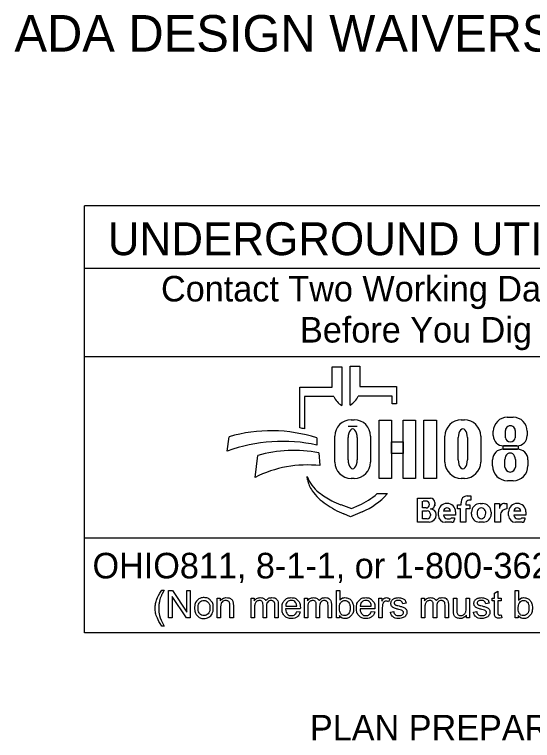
# Model space of a CAD drawing. Extents: x -4 to 116, y -17 to 29.
# Drawn here: x 86.475 to 89.311, y 9.561 to 13.536 of the extents above; entities that cross this region are included whole.
import ezdxf

# ---------------------------------------------------------------- set-up
doc = ezdxf.new("R2010")
doc.units = 0
doc.layers.add('SH_Data', color=7, linetype='Continuous')
doc.layers.add('SH_Text', color=7, linetype='Continuous')

msp = doc.modelspace()

# ---------------------------------------------------------------- linework, layer by layer
at = {"layer": 'SH_Data'}
for p, q in [((86.8574, 10.1506), (86.8574, 12.4881)), ((91.1074, 12.4881), (86.8574, 12.4881)), ((86.8574, 12.1466), (91.1074, 12.1466)), ((86.8574, 11.6632), (91.1074, 11.6632)), ((91.1074, 10.6685), (86.8574, 10.6685)), ((91.1074, 10.1506), (86.8574, 10.1506))]:
    msp.add_line(p, q, dxfattribs=at)
at = {"layer": 'SH_Text'}
for p, q in [((88.3127, 11.3979), (88.3127, 11.61)), ((88.3127, 11.61), (88.3663, 11.61)), ((88.3663, 11.61), (88.3663, 11.4985)), ((88.2134, 11.4961), (88.2134, 11.6076)), ((88.2134, 11.6076), (88.267, 11.6076)), ((88.267, 11.6076), (88.267, 11.3956)), ((88.0374, 11.2723), (88.0374, 11.4961)), ((88.0374, 11.4961), (88.2134, 11.4961)), ((88.3663, 11.4985), (88.5656, 11.4985)), ((88.5656, 11.4985), (88.5656, 11.4046)), ((88.0627, 11.4447), (88.0627, 11.2678)), ((88.2238, 11.4447), (88.0627, 11.4447)), ((88.5423, 11.447), (88.3559, 11.447)), ((88.5423, 11.4046), (88.5423, 11.447)), ((88.5656, 11.4046), (88.5423, 11.4046)), ((89.1729, 11.331), (89.2057, 11.331)), ((88.3184, 11.317), (88.3349, 11.317)), ((88.9214, 11.317), (88.938, 11.317)), ((88.3516, 11.2799), (88.3018, 11.2799)), ((89.0966, 11.2303), (89.0966, 11.2546)), ((89.1628, 11.219), (89.1628, 11.2583)), ((89.217, 11.2583), (89.217, 11.219)), ((89.282, 11.2546), (89.282, 11.2303)), ((87.6401, 11.1459), (87.6494, 11.2241)), ((88.1307, 11.2176), (88.1307, 11.1788)), ((88.2289, 11.0855), (88.2289, 11.2275)), ((88.3018, 11.0969), (88.3018, 11.2192)), ((88.3516, 11.2192), (88.3516, 11.0969)), ((88.4244, 11.2275), (88.4244, 11.0855)), ((88.8319, 11.0855), (88.8319, 11.2275)), ((88.9049, 11.0969), (88.9049, 11.2192)), ((88.9546, 11.2192), (88.9546, 11.0969)), ((89.0274, 11.2275), (89.0274, 11.0855)), ((89.226, 11.1743), (89.1526, 11.1743)), ((88.1407, 11.137), (88.1469, 11.066)), ((89.1508, 11.156), (89.2282, 11.156)), ((87.7919, 11.0014), (87.8066, 11.1216)), ((89.0929, 11.0641), (89.0929, 11.0982)), ((89.1604, 11.0582), (89.1604, 11.0991)), ((89.2173, 11.0991), (89.2173, 11.0582)), ((89.286, 11.0982), (89.286, 11.0641)), ((88.0796, 10.9885), (88.0765, 11.0064)), ((88.3349, 10.996), (88.3184, 10.996)), ((88.938, 10.996), (88.9214, 10.996)), ((89.2051, 10.9832), (89.1739, 10.9832)), ((88.4599, 10.9126), (88.5173, 10.9126)), ((88.9537, 10.9004), (88.9732, 10.9004)), ((88.9732, 10.9004), (88.9732, 10.8774)), ((88.6812, 10.7569), (88.6812, 10.8876)), ((88.6812, 10.8876), (88.7523, 10.8876)), ((88.7091, 10.8341), (88.7091, 10.8711)), ((88.7343, 10.8711), (88.7131, 10.8711)), ((88.7761, 10.8639), (88.7761, 10.856)), ((88.9205, 10.852), (88.9205, 10.8625)), ((88.9466, 10.8605), (88.9466, 10.852)), ((88.9732, 10.8769), (88.9631, 10.8769)), ((89.025, 10.8586), (89.0371, 10.8586)), ((89.1052, 10.7557), (89.1052, 10.8584)), ((89.1052, 10.8584), (89.1298, 10.8584)), ((89.1298, 10.8584), (89.1298, 10.8315)), ((89.157, 10.8584), (89.1709, 10.8584)), ((89.1709, 10.8584), (89.1709, 10.8287)), ((88.2614, 10.8523), (88.3209, 10.8318)), ((88.3209, 10.8318), (88.3619, 10.8496)), ((88.7285, 10.8341), (88.7091, 10.8341)), ((88.7091, 10.7747), (88.7091, 10.8176)), ((88.7091, 10.8176), (88.7347, 10.8176)), ((88.8623, 10.8161), (88.8238, 10.8161)), ((88.9011, 10.829), (88.9011, 10.852)), ((88.9011, 10.852), (88.9205, 10.852)), ((88.9161, 10.829), (88.9011, 10.829)), ((88.9161, 10.7557), (88.9161, 10.829)), ((88.9466, 10.852), (88.9681, 10.852)), ((88.9681, 10.829), (88.9466, 10.829)), ((88.9466, 10.829), (88.9466, 10.7557)), ((88.9681, 10.852), (88.9681, 10.829)), ((89.2472, 10.8161), (89.2087, 10.8161)), ((88.3148, 10.7848), (88.2775, 10.8012)), ((88.3781, 10.8122), (88.3148, 10.7848)), ((88.7344, 10.7747), (88.7091, 10.7747)), ((88.7528, 10.7995), (88.7528, 10.7931)), ((88.7842, 10.7966), (88.7842, 10.7962)), ((88.7957, 10.7937), (88.7957, 10.8121)), ((88.8902, 10.7944), (88.8238, 10.7944)), ((88.8447, 10.7752), (88.8589, 10.7752)), ((88.8674, 10.7807), (88.8843, 10.7807)), ((88.8843, 10.7807), (88.8843, 10.7709)), ((88.8902, 10.8121), (88.8902, 10.7944)), ((88.9771, 10.8), (88.9771, 10.8108)), ((89.0849, 10.8108), (89.0849, 10.8)), ((89.1357, 10.7938), (89.1357, 10.7557)), ((89.1806, 10.7937), (89.1806, 10.8121)), ((89.2752, 10.7944), (89.2087, 10.7944)), ((89.2297, 10.7752), (89.2438, 10.7752)), ((89.2524, 10.7807), (89.2692, 10.7807)), ((89.2692, 10.7807), (89.2692, 10.7709)), ((89.2752, 10.8121), (89.2752, 10.7944)), ((88.7448, 10.7569), (88.6812, 10.7569)), ((88.8691, 10.7557), (88.8337, 10.7557)), ((88.9466, 10.7557), (88.9161, 10.7557)), ((89.0421, 10.7572), (89.0199, 10.7572)), ((89.1357, 10.7557), (89.1052, 10.7557)), ((89.254, 10.7557), (89.2186, 10.7557))]:
    msp.add_line(p, q, dxfattribs=at)
for points in [[(88.4708, 11.3159), (88.5388, 11.3159), (88.5388, 10.9959), (88.4708, 10.9959)], [(88.603, 11.3159), (88.6709, 11.3159), (88.6709, 10.9959), (88.603, 10.9959)], [(88.7163, 11.3159), (88.785, 11.3159), (88.785, 10.9959), (88.7163, 10.9959)], [(88.5388, 11.196), (88.603, 11.196), (88.603, 11.132), (88.5388, 11.132)], [(89.1505, 11.1744), (89.2322, 11.1744), (89.2322, 11.1559), (89.1505, 11.1559)]]:
    msp.add_lwpolyline(points, close=True, dxfattribs=at)
for points in [[(87.282, 10.3844), (87.2951, 10.3844)], [(87.3187, 10.2318), (87.3187, 10.3819), (87.339, 10.3819), (87.418, 10.264), (87.418, 10.3819), (87.437, 10.3819), (87.437, 10.2318), (87.4167, 10.2318), (87.3377, 10.3497), (87.3377, 10.2318), (87.3187, 10.2318)], [(88.2542, 10.2318), (88.2371, 10.2318), (88.2371, 10.3819), (88.2555, 10.3819), (88.2555, 10.3284)], [(89.1031, 10.2636), (89.1031, 10.3263), (89.0895, 10.3263), (89.0895, 10.3406), (89.1031, 10.3406), (89.1031, 10.3675), (89.1215, 10.3786), (89.1215, 10.3406), (89.14, 10.3406), (89.14, 10.3263), (89.1215, 10.3263), (89.1215, 10.2625)], [(89.2332, 10.2318), (89.2162, 10.2318), (89.2162, 10.3819), (89.2346, 10.3819), (89.2346, 10.3284)], [(87.5847, 10.2318), (87.5847, 10.3406), (87.6013, 10.3406), (87.6013, 10.3251)], [(87.7711, 10.2318), (87.7711, 10.3406), (87.7876, 10.3406), (87.7876, 10.3252)], [(88.0625, 10.2318), (88.0625, 10.3406), (88.0789, 10.3406), (88.0789, 10.3252)], [(88.4702, 10.2318), (88.4702, 10.3406), (88.4868, 10.3406), (88.4868, 10.3241)], [(88.5293, 10.3371), (88.5228, 10.3201)], [(88.7035, 10.2318), (88.7035, 10.3406), (88.7199, 10.3406), (88.7199, 10.3252)], [(88.8778, 10.2732), (88.8778, 10.3406), (88.8962, 10.3406), (88.8962, 10.2803)], [(88.9475, 10.2823), (88.9475, 10.3406), (88.9659, 10.3406), (88.9659, 10.2318), (88.9494, 10.2318)], [(87.673, 10.2987), (87.673, 10.2318), (87.6546, 10.2318), (87.6546, 10.2979)], [(87.8542, 10.2949), (87.8542, 10.2318), (87.8357, 10.2318), (87.8357, 10.3024)], [(87.9186, 10.3064), (87.9186, 10.2318), (87.9002, 10.2318), (87.9002, 10.3003)], [(88.1455, 10.2949), (88.1455, 10.2318), (88.1271, 10.2318), (88.1271, 10.3024)], [(88.21, 10.3064), (88.21, 10.2318), (88.1916, 10.2318), (88.1916, 10.3003)], [(88.6192, 10.3124), (88.6012, 10.31)], [(88.7865, 10.2949), (88.7865, 10.2318), (88.7681, 10.2318), (88.7681, 10.3024)], [(88.851, 10.3064), (88.851, 10.2318), (88.8326, 10.2318), (88.8326, 10.3003)], [(89.0738, 10.3124), (89.0557, 10.31)], [(87.6031, 10.2911), (87.6031, 10.2318), (87.5847, 10.2318)], [(87.7895, 10.2882), (87.7895, 10.2318), (87.7711, 10.2318)], [(88.0398, 10.2814), (87.9587, 10.2814)], [(87.9597, 10.2965), (88.0205, 10.2965)], [(88.0203, 10.2669), (88.0393, 10.2645)], [(88.0809, 10.2882), (88.0809, 10.2318), (88.0625, 10.2318)], [(88.4478, 10.2814), (88.3667, 10.2814)], [(88.3677, 10.2965), (88.4285, 10.2965)], [(88.4283, 10.2669), (88.4473, 10.2645)], [(88.4887, 10.2888), (88.4887, 10.2318), (88.4702, 10.2318)], [(88.5328, 10.2643), (88.551, 10.2671)], [(88.7219, 10.2882), (88.7219, 10.2318), (88.7035, 10.2318)], [(88.9874, 10.2643), (89.0056, 10.2671)], [(88.2542, 10.2454), (88.2542, 10.2318)], [(88.9494, 10.2318), (88.9494, 10.2478)], [(89.14, 10.2482), (89.1426, 10.2319)], [(89.2332, 10.2454), (89.2332, 10.2318)], [(87.2951, 10.1876), (87.282, 10.1876)]]:
    msp.add_lwpolyline(points, dxfattribs=at)
for centre, radius, start, end in [((88.3151, 11.4815), 0.0985, 201.9296, 240.7469), ((88.2646, 11.4838), 0.0985, 299.2531, 338.0704), ((89.1729, 11.2546), 0.0763, 90, 180), ((89.2057, 11.2546), 0.0763, 0, 90), ((88.3184, 11.2275), 0.0895, 90, 180), ((88.3349, 11.2275), 0.0895, 0, 90), ((88.9214, 11.2275), 0.0895, 90, 180), ((88.938, 11.2275), 0.0895, 0, 90), ((87.8795, 10.438), 0.8191, 72.1402, 106.3144), ((87.9093, 10.4633), 0.8191, 79.2074, 81.0007), ((89.1526, 11.2303), 0.056, 180, 270), ((89.226, 11.2303), 0.056, 270, 0), ((87.9426, 10.3069), 0.8919, 77.8238, 109.8274), ((88.0065, 10.4172), 0.7322, 79.44, 105.8467), ((89.1508, 11.0982), 0.0579, 90, 180), ((89.2282, 11.0982), 0.0579, 0, 90), ((88.0785, 10.434), 0.6357, 83.8248, 116.8021), ((88.3184, 11.0855), 0.0895, 180, 270), ((88.3349, 11.0855), 0.0895, 270, 0), ((88.9214, 11.0855), 0.0895, 180, 270), ((88.938, 11.0855), 0.0895, 270, 0), ((89.1739, 11.0641), 0.081, 180, 270), ((89.2051, 11.0641), 0.081, 270, 0), ((88.2639, 11.0785), 0.2008, 201.0457, 232.5314), ((88.2209, 11.0126), 0.1433, 189.6817, 216.0884), ((88.3546, 11.1101), 0.3088, 216.0884, 235.7167), ((88.4565, 11.3298), 0.5173, 232.5314, 241.794), ((88.2185, 11.1801), 0.3602, 293.4582, 312.0712), ((88.2185, 11.1801), 0.401, 293.4582, 317.8286), ((88.9537, 10.8669), 0.0335, 90, 187.5187), ((88.5211, 11.3543), 0.6044, 235.7167, 246.2325), ((88.3713, 11.1709), 0.3371, 241.794, 250.9821), ((88.7285, 10.8529), 0.0187, 270, 2.0582), ((88.7304, 10.8542), 0.0169, 357.8325, 90), ((88.7519, 10.8531), 0.0243, 270, 6.6529), ((88.7523, 10.8639), 0.0238, 0, 90), ((88.843, 10.8121), 0.0473, 0, 180), ((88.9631, 10.8605), 0.0165, 90, 180), ((89.025, 10.8108), 0.0478, 90, 180), ((89.0371, 10.8108), 0.0478, 0, 90), ((89.1567, 10.8315), 0.0269, 89.2449, 180), ((89.2279, 10.8121), 0.0473, 0, 180), ((88.7347, 10.7995), 0.0181, 0, 90), ((88.7521, 10.7967), 0.0321, 4.0748, 90), ((88.7625, 10.8517), 0.0175, 347.4023, 0), ((88.843, 10.8151), 0.0193, 2.9632, 177.0368), ((89.1706, 10.7938), 0.0349, 89.6033, 180), ((89.2279, 10.8151), 0.0193, 2.9632, 177.0368), ((88.7344, 10.7931), 0.0184, 270, 0), ((88.7448, 10.7962), 0.0393, 270, 0), ((88.7512, 10.7966), 0.033, 0, 11.7502), ((88.8337, 10.7937), 0.038, 180, 270), ((88.8447, 10.7962), 0.021, 184.827, 270), ((88.8589, 10.7846), 0.00938, 270, 335.9979), ((89.0199, 10.8), 0.0428, 180, 270), ((89.0421, 10.8), 0.0428, 270, 0), ((89.2186, 10.7937), 0.038, 180, 270), ((89.2297, 10.7962), 0.021, 184.827, 270), ((89.2438, 10.7846), 0.00938, 270, 335.9979), ((88.8691, 10.7709), 0.0152, 270, 0), ((89.254, 10.7709), 0.0152, 270, 0)]:
    msp.add_arc(centre, radius, start, end, dxfattribs=at)
for centre, major_axis, ratio, start_param, end_param in [((88.3267, 11.2192), (0, 0.0484), 0.514403, 4.712389, 7.853982), ((88.9298, 11.2192), (0, 0.0484), 0.514403, 4.712389, 7.853982), ((89.1899, 11.2583), (0.0271, 0), 0.969373, 0, 3.141593), ((89.1899, 11.219), (0.0271, 0), 0.818453, 3.141593, 6.283185), ((89.1889, 11.0991), (0, 0.0358), 0.794529, 4.712389, 7.853982), ((88.3267, 11.0969), (0, 0.0484), 0.514403, 1.570796, 4.712389), ((88.9298, 11.0969), (0, 0.0484), 0.514403, 1.570796, 4.712389), ((89.1889, 11.0582), (0.0284, 0), 0.959837, 3.141593, 6.283185), ((89.0315, 10.8054), (0, 0.029), 0.832186, 4.712389, 7.853982), ((89.0315, 10.8054), (0, 0.0302), 0.797287, 1.570796, 4.712389)]:
    msp.add_ellipse(centre, major_axis=major_axis, ratio=ratio, start_param=start_param, end_param=end_param, dxfattribs=at)
for points in [[(87.282, 10.1876), (87.2667, 10.2068), (87.2561, 10.2327), (87.2456, 10.2585), (87.2456, 10.2861), (87.2456, 10.3105), (87.2535, 10.3328), (87.2627, 10.3587), (87.282, 10.3844)], [(87.2951, 10.3844), (87.2828, 10.3631), (87.2788, 10.354), (87.2726, 10.3399), (87.269, 10.3245), (87.2646, 10.3054), (87.2646, 10.286), (87.2646, 10.2367), (87.2951, 10.1876)], [(87.4612, 10.2862), (87.4612, 10.3164), (87.478, 10.3309), (87.492, 10.343), (87.5122, 10.343), (87.5346, 10.343), (87.5488, 10.3283), (87.563, 10.3136), (87.563, 10.2877), (87.563, 10.2667), (87.5568, 10.2547), (87.5505, 10.2427), (87.5384, 10.236), (87.5264, 10.2294), (87.5122, 10.2294), (87.4893, 10.2294), (87.4753, 10.244), (87.4612, 10.2586), (87.4612, 10.2862)], [(87.6013, 10.3251), (87.6132, 10.343), (87.6359, 10.343), (87.6457, 10.343), (87.6539, 10.3395), (87.6622, 10.3359), (87.6663, 10.3302), (87.6704, 10.3245), (87.672, 10.3166), (87.673, 10.3115), (87.673, 10.2987)], [(87.7876, 10.3252), (87.7927, 10.3333), (87.8012, 10.3381), (87.8097, 10.343), (87.8206, 10.343), (87.8327, 10.343), (87.8404, 10.338), (87.8481, 10.3329), (87.8513, 10.3239), (87.8642, 10.343), (87.885, 10.343), (87.9012, 10.343), (87.9099, 10.334), (87.9186, 10.3251), (87.9186, 10.3064)], [(88.0393, 10.2645), (88.0348, 10.2478), (88.0226, 10.2386), (88.0104, 10.2294), (87.9915, 10.2294), (87.9676, 10.2294), (87.9537, 10.2441), (87.9397, 10.2587), (87.9397, 10.2853), (87.9397, 10.3127), (87.9538, 10.3279), (87.9679, 10.343), (87.9905, 10.343), (88.0123, 10.343), (88.0261, 10.3282), (88.0399, 10.3133), (88.0399, 10.2864), (88.0399, 10.2847), (88.0398, 10.2814)], [(88.0789, 10.3252), (88.0841, 10.3333), (88.0926, 10.3381), (88.1011, 10.343), (88.1119, 10.343), (88.124, 10.343), (88.1318, 10.338), (88.1395, 10.3329), (88.1427, 10.3239), (88.1556, 10.343), (88.1763, 10.343), (88.1925, 10.343), (88.2013, 10.334), (88.21, 10.3251), (88.21, 10.3064)], [(88.2555, 10.3284), (88.2672, 10.343), (88.2853, 10.343), (88.2954, 10.343), (88.3043, 10.339), (88.3133, 10.3349), (88.3191, 10.3276), (88.3249, 10.3203), (88.3281, 10.3099), (88.3314, 10.2996), (88.3314, 10.2878), (88.3314, 10.2599), (88.3176, 10.2446), (88.3038, 10.2294), (88.2844, 10.2294), (88.2651, 10.2294), (88.2542, 10.2454)], [(88.4473, 10.2645), (88.4428, 10.2478), (88.4306, 10.2386), (88.4184, 10.2294), (88.3995, 10.2294), (88.3756, 10.2294), (88.3617, 10.2441), (88.3477, 10.2587), (88.3477, 10.2853), (88.3477, 10.3127), (88.3618, 10.3279), (88.3759, 10.343), (88.3985, 10.343), (88.4203, 10.343), (88.4341, 10.3282), (88.4479, 10.3133), (88.4479, 10.2864), (88.4479, 10.2847), (88.4478, 10.2814)], [(88.4868, 10.3241), (88.4932, 10.3357), (88.4986, 10.3393), (88.5039, 10.343), (88.5104, 10.343), (88.5197, 10.343), (88.5293, 10.3371)], [(88.551, 10.2671), (88.5526, 10.2562), (88.5596, 10.2503), (88.5667, 10.2445), (88.5793, 10.2445), (88.592, 10.2445), (88.5982, 10.2496), (88.6044, 10.2548), (88.6044, 10.2618), (88.6044, 10.2681), (88.5989, 10.2717), (88.5951, 10.2741), (88.58, 10.2779), (88.5597, 10.283), (88.5519, 10.2868), (88.544, 10.2905), (88.54, 10.2971), (88.5359, 10.3037), (88.5359, 10.3117), (88.5359, 10.319), (88.5393, 10.3251), (88.5426, 10.3313), (88.5483, 10.3354), (88.5527, 10.3386), (88.5601, 10.3408), (88.5675, 10.343), (88.5761, 10.343), (88.5889, 10.343), (88.5986, 10.3393), (88.6083, 10.3356), (88.6129, 10.3293), (88.6175, 10.323), (88.6192, 10.3124)], [(88.7199, 10.3252), (88.7251, 10.3333), (88.7336, 10.3381), (88.7421, 10.343), (88.7529, 10.343), (88.765, 10.343), (88.7728, 10.338), (88.7805, 10.3329), (88.7837, 10.3239), (88.7966, 10.343), (88.8173, 10.343), (88.8335, 10.343), (88.8423, 10.334), (88.851, 10.3251), (88.851, 10.3064)], [(89.0056, 10.2671), (89.0072, 10.2562), (89.0142, 10.2503), (89.0212, 10.2445), (89.0339, 10.2445), (89.0466, 10.2445), (89.0528, 10.2496), (89.0589, 10.2548), (89.0589, 10.2618), (89.0589, 10.2681), (89.0535, 10.2717), (89.0497, 10.2741), (89.0346, 10.2779), (89.0143, 10.283), (89.0065, 10.2868), (88.9986, 10.2905), (88.9946, 10.2971), (88.9905, 10.3037), (88.9905, 10.3117), (88.9905, 10.319), (88.9938, 10.3251), (88.9972, 10.3313), (89.0029, 10.3354), (89.0072, 10.3386), (89.0147, 10.3408), (89.0221, 10.343), (89.0306, 10.343), (89.0434, 10.343), (89.0531, 10.3393), (89.0628, 10.3356), (89.0675, 10.3293), (89.0721, 10.323), (89.0738, 10.3124)], [(89.2346, 10.3284), (89.2463, 10.343), (89.2644, 10.343), (89.2744, 10.343), (89.2834, 10.339), (89.2924, 10.3349), (89.2981, 10.3276), (89.3039, 10.3203), (89.3072, 10.3099), (89.3105, 10.2996), (89.3105, 10.2878), (89.3105, 10.2599), (89.2967, 10.2446), (89.2828, 10.2294), (89.2635, 10.2294), (89.2442, 10.2294), (89.2332, 10.2454)], [(87.4802, 10.2862), (87.4802, 10.2653), (87.4893, 10.2549), (87.4984, 10.2445), (87.5122, 10.2445), (87.5259, 10.2445), (87.535, 10.2549), (87.5441, 10.2654), (87.5441, 10.2868), (87.5441, 10.307), (87.5349, 10.3174), (87.5258, 10.3278), (87.5122, 10.3278), (87.4984, 10.3278), (87.4893, 10.3174), (87.4802, 10.3071), (87.4802, 10.2862)], [(87.6546, 10.2979), (87.6546, 10.3092), (87.6525, 10.3147), (87.6503, 10.3203), (87.6448, 10.3237), (87.6393, 10.327), (87.632, 10.327), (87.6202, 10.327), (87.6117, 10.3195), (87.6031, 10.312), (87.6031, 10.2911)], [(87.8357, 10.3024), (87.8357, 10.3147), (87.8312, 10.3208), (87.8267, 10.327), (87.8165, 10.327), (87.8087, 10.327), (87.8021, 10.3229), (87.7955, 10.3188), (87.7925, 10.3109), (87.7895, 10.303), (87.7895, 10.2882)], [(87.9002, 10.3003), (87.9002, 10.3113), (87.8984, 10.3162), (87.8966, 10.321), (87.8919, 10.324), (87.8872, 10.327), (87.8808, 10.327), (87.8693, 10.327), (87.8618, 10.3194), (87.8542, 10.3117), (87.8542, 10.2949)], [(88.0205, 10.2965), (88.0192, 10.3103), (88.0135, 10.3172), (88.0047, 10.3279), (87.9907, 10.3279), (87.978, 10.3279), (87.9693, 10.3194), (87.9606, 10.3108), (87.9597, 10.2965)], [(88.1271, 10.3024), (88.1271, 10.3147), (88.1226, 10.3208), (88.1181, 10.327), (88.1078, 10.327), (88.1001, 10.327), (88.0934, 10.3229), (88.0868, 10.3188), (88.0839, 10.3109), (88.0809, 10.303), (88.0809, 10.2882)], [(88.1916, 10.3003), (88.1916, 10.3113), (88.1898, 10.3162), (88.188, 10.321), (88.1833, 10.324), (88.1785, 10.327), (88.1722, 10.327), (88.1607, 10.327), (88.1531, 10.3194), (88.1455, 10.3117), (88.1455, 10.2949)], [(88.2539, 10.287), (88.2539, 10.2674), (88.2593, 10.2587), (88.268, 10.2445), (88.2828, 10.2445), (88.2948, 10.2445), (88.3036, 10.255), (88.3124, 10.2655), (88.3124, 10.2863), (88.3124, 10.3076), (88.304, 10.3178), (88.2956, 10.3279), (88.2836, 10.3279), (88.2715, 10.3279), (88.2627, 10.3174), (88.2539, 10.3069), (88.2539, 10.287)], [(88.4285, 10.2965), (88.4272, 10.3103), (88.4215, 10.3172), (88.4127, 10.3279), (88.3986, 10.3279), (88.3859, 10.3279), (88.3773, 10.3194), (88.3686, 10.3108), (88.3677, 10.2965)], [(88.5228, 10.3201), (88.5161, 10.324), (88.5094, 10.324), (88.5034, 10.324), (88.4986, 10.3204), (88.4938, 10.3167), (88.4917, 10.3103), (88.4887, 10.3004), (88.4887, 10.2888)], [(88.6012, 10.31), (88.5999, 10.3185), (88.594, 10.3232), (88.5881, 10.3279), (88.5774, 10.3279), (88.5647, 10.3279), (88.5592, 10.3237), (88.5538, 10.3195), (88.5538, 10.3138), (88.5538, 10.3102), (88.556, 10.3074), (88.5583, 10.3044), (88.5631, 10.3025), (88.5659, 10.3014), (88.5794, 10.2977), (88.599, 10.2925), (88.6068, 10.2892), (88.6145, 10.2859), (88.6189, 10.2795), (88.6234, 10.2732), (88.6234, 10.2638), (88.6234, 10.2545), (88.618, 10.2464), (88.6126, 10.2383), (88.6024, 10.2338), (88.5923, 10.2294), (88.5794, 10.2294), (88.5582, 10.2294), (88.5471, 10.2382), (88.5359, 10.247), (88.5328, 10.2643)], [(88.7681, 10.3024), (88.7681, 10.3147), (88.7636, 10.3208), (88.7591, 10.327), (88.7488, 10.327), (88.7411, 10.327), (88.7344, 10.3229), (88.7278, 10.3188), (88.7249, 10.3109), (88.7219, 10.303), (88.7219, 10.2882)], [(88.8326, 10.3003), (88.8326, 10.3113), (88.8308, 10.3162), (88.829, 10.321), (88.8243, 10.324), (88.8195, 10.327), (88.8132, 10.327), (88.8017, 10.327), (88.7941, 10.3194), (88.7865, 10.3117), (88.7865, 10.2949)], [(89.0557, 10.31), (89.0545, 10.3185), (89.0486, 10.3232), (89.0427, 10.3279), (89.0319, 10.3279), (89.0192, 10.3279), (89.0138, 10.3237), (89.0084, 10.3195), (89.0084, 10.3138), (89.0084, 10.3102), (89.0106, 10.3074), (89.0129, 10.3044), (89.0177, 10.3025), (89.0205, 10.3014), (89.034, 10.2977), (89.0536, 10.2925), (89.0613, 10.2892), (89.0691, 10.2859), (89.0735, 10.2795), (89.0779, 10.2732), (89.0779, 10.2638), (89.0779, 10.2545), (89.0725, 10.2464), (89.0672, 10.2383), (89.057, 10.2338), (89.0468, 10.2294), (89.034, 10.2294), (89.0128, 10.2294), (89.0016, 10.2382), (88.9905, 10.247), (88.9874, 10.2643)], [(89.233, 10.287), (89.233, 10.2674), (89.2383, 10.2587), (89.247, 10.2445), (89.2618, 10.2445), (89.2739, 10.2445), (89.2827, 10.255), (89.2915, 10.2655), (89.2915, 10.2863), (89.2915, 10.3076), (89.2831, 10.3178), (89.2746, 10.3279), (89.2627, 10.3279), (89.2506, 10.3279), (89.2418, 10.3174), (89.233, 10.3069), (89.233, 10.287)], [(87.9587, 10.2814), (87.9597, 10.2635), (87.9688, 10.254), (87.9779, 10.2445), (87.9916, 10.2445), (88.0017, 10.2445), (88.0089, 10.2498), (88.0161, 10.2552), (88.0203, 10.2669)], [(88.3667, 10.2814), (88.3677, 10.2635), (88.3768, 10.254), (88.3859, 10.2445), (88.3996, 10.2445), (88.4097, 10.2445), (88.4169, 10.2498), (88.4241, 10.2552), (88.4283, 10.2669)], [(88.9494, 10.2478), (88.9367, 10.2294), (88.9149, 10.2294), (88.9053, 10.2294), (88.897, 10.233), (88.8886, 10.2367), (88.8846, 10.2423), (88.8805, 10.2479), (88.8789, 10.256), (88.8778, 10.2614), (88.8778, 10.2732)], [(88.8962, 10.2803), (88.8962, 10.2659), (88.8973, 10.2608), (88.8991, 10.2536), (88.9047, 10.2494), (88.9103, 10.2453), (88.9186, 10.2453), (88.9269, 10.2453), (88.9342, 10.2495), (88.9414, 10.2538), (88.9445, 10.2611), (88.9475, 10.2684), (88.9475, 10.2823)], [(89.1426, 10.2319), (89.1348, 10.2303), (89.1287, 10.2303), (89.1187, 10.2303), (89.1131, 10.2335), (89.1076, 10.2366), (89.1054, 10.2418), (89.1031, 10.247), (89.1031, 10.2636)], [(89.1215, 10.2625), (89.1215, 10.2546), (89.1225, 10.2524), (89.1235, 10.2501), (89.1257, 10.2488), (89.1279, 10.2474), (89.1319, 10.2474), (89.135, 10.2474), (89.14, 10.2482)]]:
    msp.add_open_spline(points, degree=3, dxfattribs=at)

# ---------------------------------------------------------------- texts
for s, height, p in [('ADA DESIGN WAIVERS', 0.2, (86.4743, 13.3335)), ('UNDERGROUND UTILITIES', 0.18, (86.9855, 12.2185)), ('Contact Two Working Days', 0.14, (87.277, 11.965)), ('Before You Dig', 0.14, (88.0382, 11.74)), ('OHIO811, 8-1-1, or 1-800-362-2764', 0.14, (86.9018, 10.4485)), ('PLAN PREPARED BY:', 0.14, (88.0923, 9.5609))]:
    msp.add_text(s, height=height, dxfattribs=at).set_placement(p)

doc.saveas('drawing.dxf')
